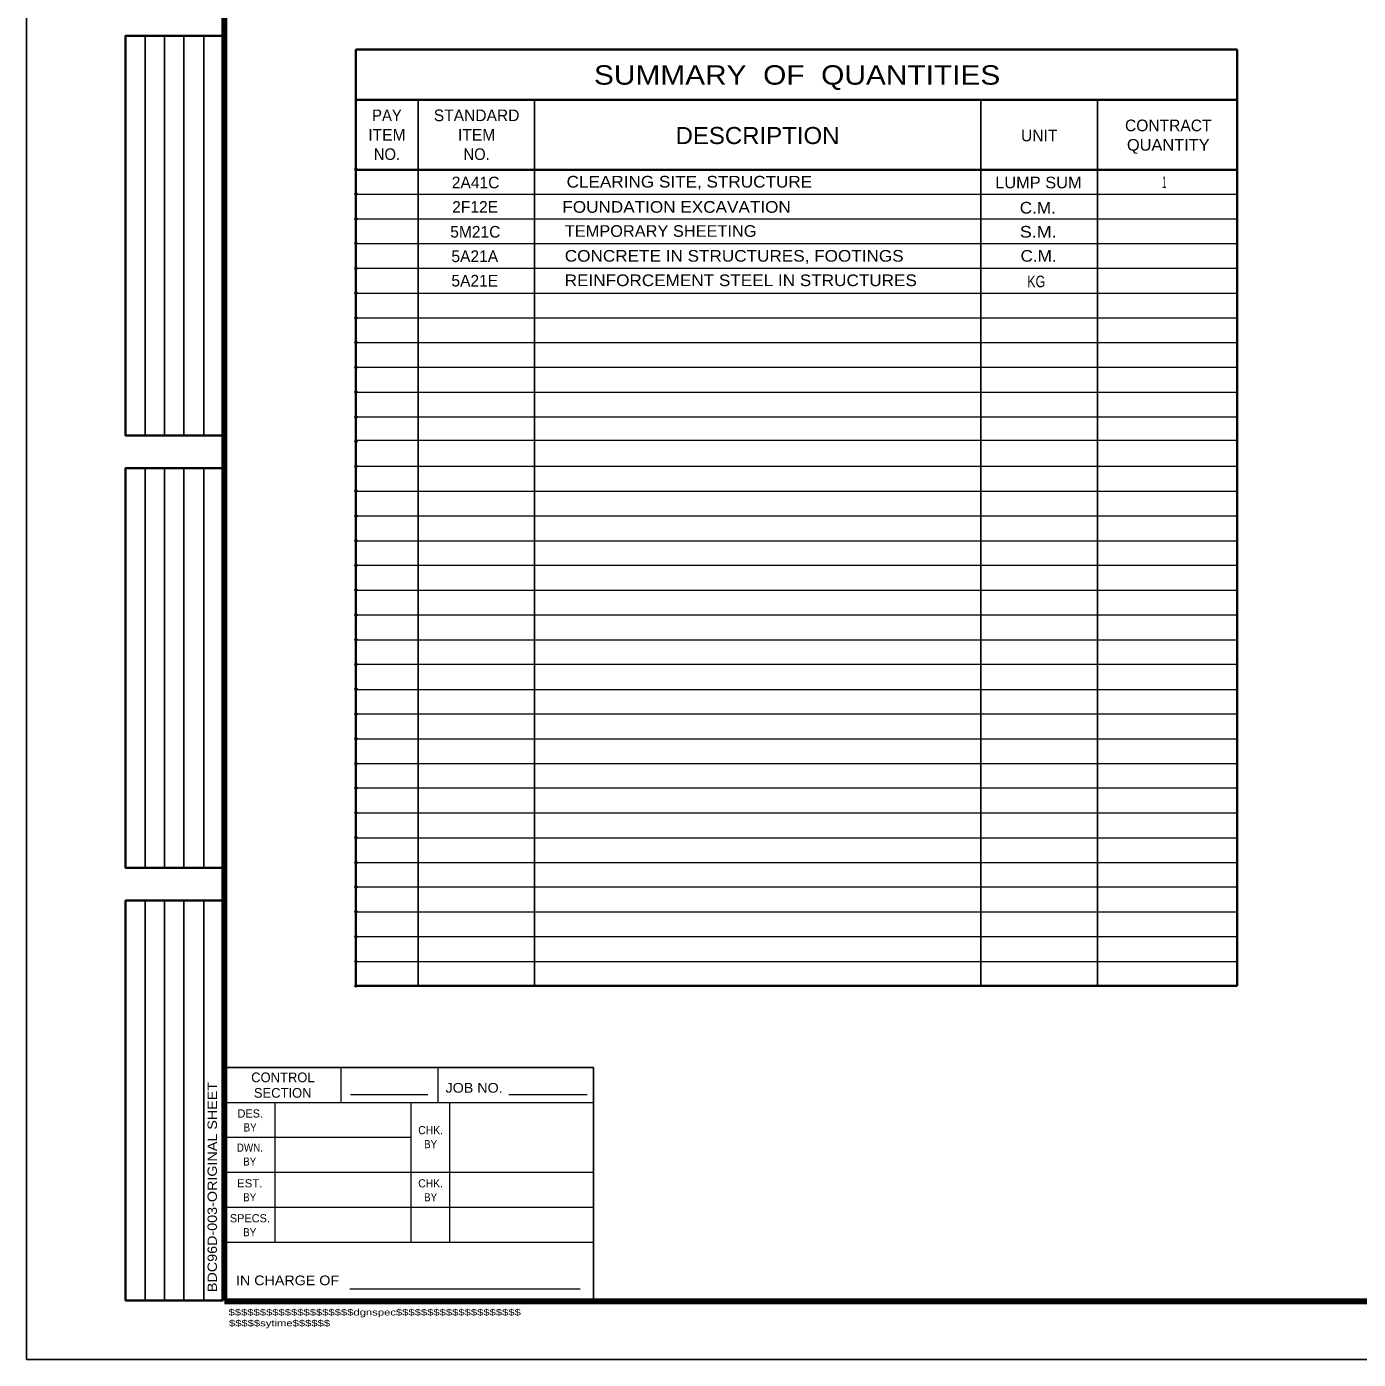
# Model space of a CAD drawing. Extents: x 312601.858 to 312602.699, y 144420.109 to 144420.704.
# Drawn here: x 312601.8578 to 312602.2008, y 144420.1095 to 144420.4528 of the extents above; entities that cross this region are included whole.
import ezdxf
from ezdxf.enums import TextEntityAlignment as Align

# ---------------------------------------------------------------- set-up
doc = ezdxf.new("R2010")
doc.units = 0
doc.header["$LTSCALE"] = 0.0012
doc.header["$PDMODE"] = 32
doc.header["$PDSIZE"] = 0.0006
for name, color, linetype, lineweight in [('1', 7, 'Continuous', 13), ('2', 7, 'Continuous', 25), ('39', 7, 'Continuous', 13), ('60', 7, 'Continuous', 25)]:
    doc.layers.add(name, color=color, linetype=linetype, lineweight=lineweight)

msp = doc.modelspace()

# ---------------------------------------------------------------- linework, layer by layer
at = {"layer": '1', "lineweight": 35}
for p, q in [((312601.9426, 144420.2057), (312601.9426, 144420.447)), ((312601.9426, 144420.447), (312602.1696, 144420.447)), ((312602.1696, 144420.2057), (312602.1696, 144420.447)), ((312601.9426, 144420.434), (312602.1696, 144420.434)), ((312601.9426, 144420.416), (312602.1696, 144420.416)), ((312601.9426, 144420.2057), (312602.1696, 144420.2057))]:
    msp.add_line(p, q, dxfattribs=at)
at = {"layer": '1', "lineweight": 25}
for p, q in [((312601.9586, 144420.2057), (312601.9586, 144420.434)), ((312601.9886, 144420.2057), (312601.9886, 144420.434)), ((312602.1036, 144420.2057), (312602.1036, 144420.434)), ((312602.1336, 144420.2057), (312602.1336, 144420.434)), ((312602.1336, 144420.2057), (312602.1336, 144420.4247))]:
    msp.add_line(p, q, dxfattribs=at)
at = {"layer": '1'}
for p, q in [((312601.9426, 144420.4097), (312602.1696, 144420.4097)), ((312601.9426, 144420.4033), (312602.1696, 144420.4033)), ((312601.9426, 144420.397), (312602.1696, 144420.397)), ((312601.9426, 144420.3906), (312602.1696, 144420.3906)), ((312601.9426, 144420.3842), (312602.1696, 144420.3842)), ((312601.9426, 144420.3778), (312602.1696, 144420.3778)), ((312601.9426, 144420.3715), (312602.1696, 144420.3715)), ((312601.9426, 144420.3651), (312602.1696, 144420.3651)), ((312601.9426, 144420.3587), (312602.1696, 144420.3587)), ((312601.9426, 144420.3523), (312602.1696, 144420.3523)), ((312601.9426, 144420.3463), (312602.1696, 144420.3463)), ((312601.9426, 144420.3396), (312602.1696, 144420.3396)), ((312601.9426, 144420.3332), (312602.1696, 144420.3332)), ((312601.9426, 144420.3268), (312602.1696, 144420.3268)), ((312601.9426, 144420.3204), (312602.1696, 144420.3204)), ((312601.9426, 144420.3141), (312602.1696, 144420.3141)), ((312601.9426, 144420.3077), (312602.1696, 144420.3077)), ((312601.9426, 144420.3013), (312602.1696, 144420.3013)), ((312601.9426, 144420.2949), (312602.1696, 144420.2949)), ((312601.9426, 144420.2886), (312602.1696, 144420.2886)), ((312601.9426, 144420.2821), (312602.1696, 144420.2821)), ((312601.9426, 144420.2758), (312602.1696, 144420.2758)), ((312601.9426, 144420.2694), (312602.1696, 144420.2694)), ((312601.9426, 144420.263), (312602.1696, 144420.263)), ((312601.9426, 144420.2567), (312602.1696, 144420.2567)), ((312601.9426, 144420.2503), (312602.1696, 144420.2503)), ((312601.9426, 144420.2439), (312602.1696, 144420.2439)), ((312601.9426, 144420.2375), (312602.1696, 144420.2375)), ((312601.9426, 144420.2312), (312602.1696, 144420.2312)), ((312601.9426, 144420.2248), (312602.1696, 144420.2248)), ((312601.9426, 144420.2184), (312602.1696, 144420.2184)), ((312601.9426, 144420.212), (312602.1696, 144420.212))]:
    msp.add_line(p, q, dxfattribs=at)
for p in [(312601.9426, 144420.4161), (312601.9426, 144420.4097), (312601.9426, 144420.4033), (312601.9426, 144420.397), (312601.9426, 144420.3906), (312601.9426, 144420.3842), (312601.9426, 144420.3778), (312601.9426, 144420.3715), (312601.9426, 144420.3651), (312601.9426, 144420.3587), (312601.9426, 144420.3523), (312601.9426, 144420.346), (312601.9426, 144420.3396), (312601.9426, 144420.3332), (312601.9426, 144420.3268), (312601.9426, 144420.3204), (312601.9426, 144420.3141), (312601.9426, 144420.3077), (312601.9426, 144420.3013), (312601.9426, 144420.2949), (312601.9426, 144420.2886), (312601.9426, 144420.2822), (312601.9426, 144420.2758), (312601.9426, 144420.2694), (312601.9426, 144420.263), (312601.9426, 144420.2567), (312601.9426, 144420.2503), (312601.9426, 144420.2439), (312601.9426, 144420.2375), (312601.9426, 144420.2312), (312601.9426, 144420.2248), (312601.9426, 144420.2184), (312601.9426, 144420.212), (312601.9426, 144420.2057)]:
    msp.add_point(p, dxfattribs=at)
at = {"layer": '39', "lineweight": 25}
for p, q in [((312601.8578, 144420.1095), (312601.8578, 144420.7035)), ((312601.9088, 144420.1847), (312602.0038, 144420.1847)), ((312602.0038, 144420.1247), (312602.0038, 144420.1847)), ((312601.8578, 144420.1095), (312602.6988, 144420.1095))]:
    msp.add_line(p, q, dxfattribs=at)
at = {"layer": '39', "lineweight": 158}
for p, q in [((312601.9088, 144420.1247), (312601.9088, 144420.6645)), ((312601.9088, 144420.1245), (312602.6838, 144420.1245))]:
    msp.add_line(p, q, dxfattribs=at)
at = {"layer": '39'}
for p, q in [((312601.9088, 144420.1247), (312601.9088, 144420.1847)), ((312601.9388, 144420.1757), (312601.9388, 144420.1847)), ((312601.9638, 144420.1757), (312601.9638, 144420.1847)), ((312601.9412, 144420.1777), (312601.9611, 144420.1777)), ((312601.982, 144420.1777), (312602.0022, 144420.1777)), ((312601.9088, 144420.1757), (312602.0038, 144420.1757)), ((312601.9218, 144420.1397), (312601.9218, 144420.1757)), ((312601.9568, 144420.1397), (312601.9568, 144420.1757)), ((312601.9668, 144420.1397), (312601.9668, 144420.1757)), ((312601.9088, 144420.1667), (312601.9568, 144420.1667)), ((312601.9088, 144420.1577), (312602.0038, 144420.1577)), ((312601.9088, 144420.1487), (312602.0038, 144420.1487)), ((312601.9088, 144420.1397), (312602.0038, 144420.1397)), ((312601.941, 144420.1277), (312602.0004, 144420.1277)), ((312601.9088, 144420.1247), (312602.0038, 144420.1247))]:
    msp.add_line(p, q, dxfattribs=at)
at = {"layer": '60'}
for p, q in [((312601.8883, 144420.3475), (312601.8883, 144420.4505)), ((312601.8933, 144420.3475), (312601.8933, 144420.4505)), ((312601.8983, 144420.3475), (312601.8983, 144420.4505)), ((312601.9034, 144420.3475), (312601.9034, 144420.4505)), ((312601.8883, 144420.2361), (312601.8883, 144420.3391)), ((312601.8933, 144420.2361), (312601.8933, 144420.3391)), ((312601.8983, 144420.2361), (312601.8983, 144420.3391)), ((312601.9034, 144420.2361), (312601.9034, 144420.3391)), ((312601.8883, 144420.1247), (312601.8883, 144420.2277)), ((312601.8933, 144420.1247), (312601.8933, 144420.2277)), ((312601.8983, 144420.1247), (312601.8983, 144420.2277)), ((312601.9034, 144420.1247), (312601.9034, 144420.2277))]:
    msp.add_line(p, q, dxfattribs=at)
at = {"layer": '60', "lineweight": 35}
for points in [[(312601.9084, 144420.3475), (312601.8833, 144420.3475), (312601.8833, 144420.4505), (312601.9084, 144420.4505)], [(312601.9084, 144420.2361), (312601.8833, 144420.2361), (312601.8833, 144420.3391), (312601.9084, 144420.3391)], [(312601.9084, 144420.1247), (312601.8833, 144420.1247), (312601.8833, 144420.2277), (312601.9084, 144420.2277)]]:
    msp.add_lwpolyline(points, dxfattribs=at)

# ---------------------------------------------------------------- texts
at = {"layer": '1'}
for s, height, p in [('CONTROL', 0.0025, (312601.9238, 144420.1809)), ('SECTION', 0.0025, (312601.92375, 144420.1769)), ('DES.', 0.0021, (312601.9154, 144420.1718)), ('SPECS.', 0.0021, (312601.9153, 144420.1448))]:
    msp.add_text(s, height=height, dxfattribs=at).set_placement(p, align=Align.CENTER)
for s, height, width, p in [('JOB NO.', 0.0025, 1.1, (312601.97305, 144420.1782)), ('BY', 0.0021, 0.9, (312601.91535, 144420.1682)), ('CHK.', 0.0021, 0.95, (312601.96185, 144420.1675)), ('DWN.', 0.0021, 0.9, (312601.9153, 144420.163)), ('BY', 0.0021, 0.9, (312601.96185, 144420.1639)), ('BY', 0.0021, 0.9, (312601.91525, 144420.1594)), ('EST.', 0.0021, 1.05, (312601.91525, 144420.1538)), ('CHK.', 0.0021, 0.95, (312601.96185, 144420.1538)), ('BY', 0.0021, 0.9, (312601.91525, 144420.1502)), ('BY', 0.0021, 0.9, (312601.96185, 144420.1502)), ('BY', 0.0021, 0.9, (312601.91525, 144420.1412)), ('IN CHARGE OF', 0.0025, 1.1, (312601.925, 144420.1286))]:
    msp.add_text(s, height=height, dxfattribs=dict(at, width=width)).set_placement(p, align=Align.CENTER)
at = {"layer": '2'}
for s, height, width, p in [('SUMMARY  OF  QUANTITIES', 0.005, 1.15, (312602.05625, 144420.4379)), ('PAY', 0.003, 0.95, (312601.9506, 144420.4285)), ('DESCRIPTION', 0.0044, 1.05, (312602.04605, 144420.4226)), ('NO.', 0.003, 0.95, (312601.9506, 144420.4185)), ('NO.', 0.003, 0.95, (312601.9737, 144420.4185)), ('QUANTITY', 0.003, 1.05, (312602.15185, 144420.4209)), ('CLEARING SITE, STRUCTURE', 0.003, 1.1, (312602.0285, 144420.4114)), ('LUMP SUM', 0.003, 1.05, (312602.1184, 144420.4112)), ('FOUNDATION EXCAVATION', 0.003, 1.1, (312602.0252, 144420.4049)), ('C.M.', 0.003, 1.1, (312602.11825, 144420.4047)), ('TEMPORARY SHEETING', 0.003, 1.05, (312602.0211, 144420.3987)), ('S.M.', 0.003, 1.15, (312602.11835, 144420.3985)), ('CONCRETE IN STRUCTURES, FOOTINGS', 0.003, 1.1, (312602.04005, 144420.3923)), ('C.M.', 0.003, 1.1, (312602.11845, 144420.3923)), ('REINFORCEMENT STEEL IN STRUCTURES', 0.003, 1.1, (312602.04175, 144420.386)), ('KG', 0.003, 0.8, (312602.11785, 144420.3857))]:
    msp.add_text(s, height=height, dxfattribs=dict(at, width=width)).set_placement(p, align=Align.CENTER)
for s, p in [('STANDARD', (312601.9737, 144420.4285)), ('CONTRACT', (312602.15185, 144420.4259)), ('ITEM', (312601.9506, 144420.4235)), ('ITEM', (312601.9737, 144420.4235)), ('UNIT', (312602.1186, 144420.4233))]:
    msp.add_text(s, height=0.003, dxfattribs=at).set_placement(p, align=Align.CENTER)
for s, p in [('2A41C', (312601.9673, 144420.4112)), ('2F12E', (312601.9674, 144420.4049)), ('5M21C', (312601.9669, 144420.3985)), ('5A21A', (312601.9672, 144420.3922)), ('5A21E', (312601.9672, 144420.3859))]:
    msp.add_text(s, height=0.003, dxfattribs=at).set_placement(p)
for s, height, width, p in [('1', 0.003, 0.45, (312602.1503, 144420.4113)), ('$$$$$$$$$$$$$$$$$$$$dgnspec$$$$$$$$$$$$$$$$$$$$', 0.001664, 1.3, (312601.9098, 144420.1208)), ('$$$$$sytime$$$$$$', 0.001664, 1.3, (312601.9099, 144420.118))]:
    msp.add_text(s, height=height, dxfattribs=dict(at, width=width)).set_placement(p)
at = {"layer": '2', "width": 1.15}
msp.add_text('BDC96D-003-ORIGINAL SHEET', height=0.0024, rotation=90, dxfattribs=at).set_placement((312601.9068, 144420.1539), align=Align.CENTER)

doc.saveas('drawing.dxf')
